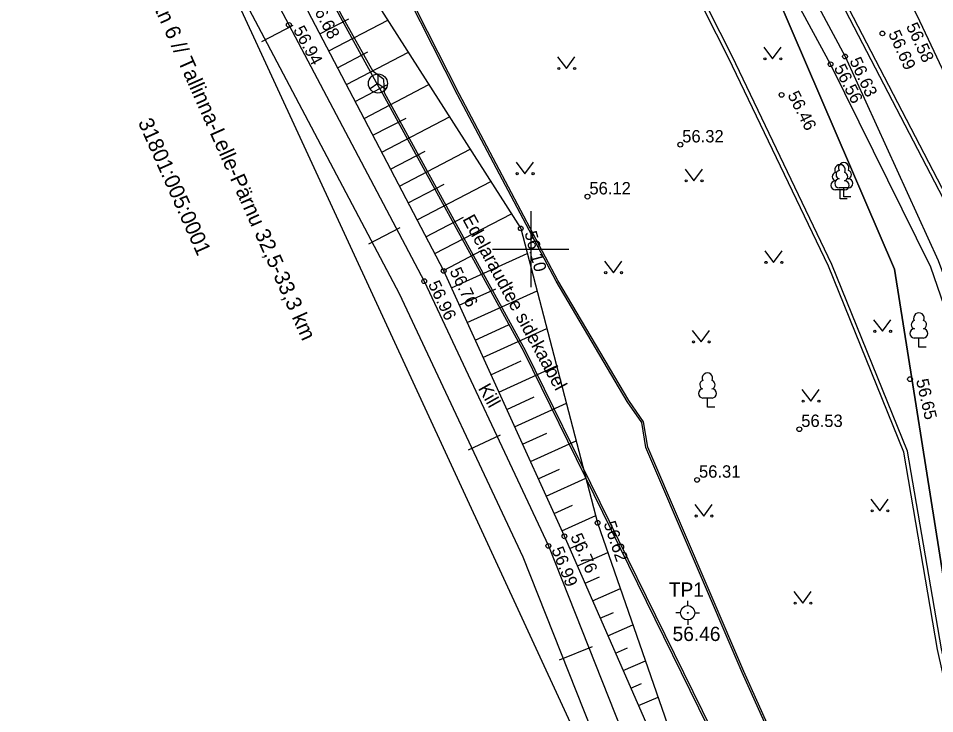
# Model space of a CAD drawing. Extents: x 542320 to 543602, y 6558748 to 6559969.
# Drawn here: x 542573.14 to 542621.18, y 6559275.64 to 6559312.11 of the extents above; entities that cross this region are included whole.
import ezdxf

# ---------------------------------------------------------------- set-up
doc = ezdxf.new("R2010")
doc.units = 0
for name, color, linetype in [('ALUSVORK', 7, 'Continuous'), ('HALJASTUS', 7, 'Continuous'), ('KORGUS-EH2000', 7, 'Continuous'), ('KPKAABEL', 7, 'Continuous'), ('mootpiir', 7, 'Continuous'), ('MPKAABEL', 7, 'Continuous'), ('PIIR', 7, 'Continuous'), ('PUU', 7, 'Continuous'), ('RDT', 7, 'Continuous'), ('RELJEEF', 7, 'Continuous'), ('SIKAEV', 7, 'Continuous'), ('SITRASS', 7, 'Continuous'), ('TEE', 7, 'Continuous'), ('VORK', 7, 'Continuous')]:
    doc.layers.add(name, color=color, linetype=linetype)

# ---------------------------------------------------------------- blocks, each defined once
blk = doc.blocks.new('VKORIS')
for p, q in [((0, 4), (0, -4)), ((-4, 0), (4, 0))]:
    blk.add_line(p, q)
blk = doc.blocks.new('SIKAEV')
for p, q in [((0, 1), (0, 0)), ((0, 0), (-0.83, -0.55)), ((0, 0), (0.83, -0.55))]:
    blk.add_line(p, q)
blk.add_circle((0, 0), 1)
blk = doc.blocks.new('LEHTP1')
for p, q in [((0.48, 0.95), (-0.48, 0.95)), ((0, 0), (0, 0.95)), ((0.76, 0), (0, 0))]:
    blk.add_line(p, q)
for centre, radius, start, end in [((0, 3.04), 0.554, 332.5799, 207.4201), ((-0.34, 2.345), 0.465, 109.02174, 253.14154), ((0.34, 2.345), 0.465, 286.85082, 70.98591), ((-0.475, 1.425), 0.475, 90.0016, 269.3953), ((0.475, 1.425), 0.475, 270.6047, 89.9984)]:
    blk.add_arc(centre, radius, start, end)
blk = doc.blocks.new('MURU')
for p, q in [((-0.927, 1.213), (0, 0)), ((0, 0), (0.891, 1.213))]:
    blk.add_line(p, q)
for centre in [(-0.802, 0), (0.856, 0)]:
    blk.add_circle(centre, 0.11)
blk = doc.blocks.new('SPYMAR')
for p, q in [((0, 0.75), (0, 1.25)), ((-0.75, 0), (-1.25, 0)), ((0.75, 0), (1.25, 0)), ((0, -0.75), (0, -1.25))]:
    blk.add_line(p, q)
for radius in [0.75, 0.044]:
    blk.add_circle((0, 0), radius)
blk = doc.blocks.new('RING02')
blk.add_circle((0, 0), 0.25)

msp = doc.modelspace()

# ---------------------------------------------------------------- linework, layer by layer
at = {"layer": 'KPKAABEL'}
for points in [[(542592.521, 6559362.446), (542597.547, 6559351.945), (542600.14, 6559344.366), (542606.118, 6559332.403), (542610.857, 6559323.162), (542616.273, 6559312.944), (542622.065, 6559301.812), (542626.969, 6559292.384), (542631.614, 6559283.754), (542633.958, 6559279.16), (542635.835, 6559275.606), (542642.325, 6559262.55)], [(542592.701, 6559362.532), (542597.732, 6559352.021), (542600.325, 6559344.443), (542606.296, 6559332.493), (542611.034, 6559323.254), (542616.45, 6559313.037), (542622.242, 6559301.904), (542627.146, 6559292.478), (542631.791, 6559283.847), (542634.136, 6559279.252), (542636.013, 6559275.697), (542642.504, 6559262.639)], [(542629.705, 6559255.548), (542624.459, 6559265.014), (542621.333, 6559278.998), (542619.565, 6559289.352), (542615.605, 6559299.115), (542610.376, 6559310.033), (542605.393, 6559319.873), (542600.368, 6559330.022), (542596.984, 6559338.198), (542596.381, 6559342.121), (542596.809, 6559346.972), (542595.758, 6559350.645), (542591.144, 6559359.29), (542590.252, 6559360.802)], [(542629.88, 6559255.645), (542624.648, 6559265.086), (542621.529, 6559279.037), (542619.758, 6559289.407), (542615.788, 6559299.196), (542610.555, 6559310.121), (542605.572, 6559319.963), (542600.55, 6559330.105), (542597.178, 6559338.252), (542596.582, 6559342.128), (542597.011, 6559346.991), (542595.944, 6559350.72), (542591.318, 6559359.388), (542590.424, 6559360.904)]]:
    msp.add_lwpolyline(points, dxfattribs=at)
at = {"layer": 'mootpiir'}
msp.add_lwpolyline([(542580.596, 6559350.501), (542576.13, 6559347.213), (542573.572, 6559344.253), (542570.527, 6559343.48), (542613.7, 6559249.972), (542615.953, 6559250.584), (542618.546, 6559251.554), (542622.286, 6559253.49), (542626.884, 6559255.347), (542629.88, 6559255.645), (542630.445, 6559256.8), (542630.818, 6559257.341), (542632.786, 6559258.084), (542634.681, 6559258.868), (542635.466, 6559259.163), (542639.905, 6559261.019), (542642.325, 6559262.55), (542647.794, 6559265.185), (542644.803, 6559292.129), (542641.558, 6559300.605), (542636.848, 6559320.338), (542627.616, 6559356.728)], dxfattribs=at)
at = {"layer": 'MPKAABEL'}
for points in [[(542622.093, 6559253.39), (542621.335, 6559255.374), (542617.705, 6559263.498), (542614.681, 6559269.795), (542611.089, 6559277.807), (542606.04, 6559289.597), (542605.819, 6559290.909), (542605.062, 6559292.013), (542601.327, 6559298.317), (542596.156, 6559308.103), (542592.302, 6559315.731), (542590.046, 6559320.195), (542585.68, 6559328.499), (542583.041, 6559333.495), (542580.391, 6559338.551), (542578.352, 6559342.398), (542575.831, 6559346.867)], [(542622.183, 6559253.436), (542621.427, 6559255.412), (542617.796, 6559263.54), (542614.772, 6559269.837), (542611.181, 6559277.847), (542606.137, 6559289.625), (542605.914, 6559290.947), (542605.146, 6559292.067), (542601.414, 6559298.366), (542596.245, 6559308.149), (542592.391, 6559315.776), (542590.135, 6559320.241), (542585.768, 6559328.546), (542583.129, 6559333.542), (542580.479, 6559338.598), (542578.44, 6559342.446), (542575.9, 6559346.947)]]:
    msp.add_lwpolyline(points, dxfattribs=at)
at = {"layer": 'PIIR'}
for points in [[(542456.68, 6559581.07), (542523.83, 6559477.46), (542537.52, 6559453.62), (542591.81, 6559358.92), (542597.79, 6559348.5), (542599.76, 6559343.89), (542619.08, 6559298.96), (542624.28, 6559266.08), (542637.46, 6559233.17), (542680, 6559143.81), (542700.43, 6559093.84), (542700.92, 6559090.29), (542704.02, 6559067.82)], [(542612.16, 6559350.51), (542632.63, 6559302.87), (542665.71, 6559205.86), (542667.87, 6559200.49), (542682.31, 6559164.31), (542683.94, 6559160.9), (542699.54, 6559124.27), (542718.47, 6559078.4), (542700.92, 6559090.29), (542700.43, 6559093.84), (542680, 6559143.81), (542637.46, 6559233.17), (542624.28, 6559266.08), (542619.08, 6559298.96), (542599.76, 6559343.89), (542612.16, 6559350.51)]]:
    msp.add_lwpolyline(points, dxfattribs=at)
at = {"layer": 'RDT'}
for points in [[(542570.527, 6559343.48), (542587.317, 6559311.762), (542594.415, 6559298.323), (542600.925, 6559284.44), (542609.327, 6559263.254), (542613.7, 6559249.972)], [(542569.237, 6559342.797), (542586.027, 6559311.079), (542593.108, 6559297.672), (542599.584, 6559283.86), (542607.954, 6559262.756), (542612.313, 6559249.515)], [(542585.902, 6559310.886), (542587.547, 6559311.755)], [(542591.507, 6559300.275), (542593.151, 6559301.144)], [(542596.731, 6559289.475), (542598.415, 6559290.265)], [(542601.506, 6559278.472), (542603.235, 6559279.158)]]:
    msp.add_lwpolyline(points, dxfattribs=at)
at = {"layer": 'RELJEEF'}
for points in [[(542611.276, 6559263.245), (542601.766, 6559284.942), (542595.436, 6559298.859), (542588.129, 6559312.865), (542578.066, 6559334.392), (542577.883, 6559336.16), (542579.736, 6559338.198), (542583.573, 6559340.233), (542588.18, 6559342.437), (542591.624, 6559344.187)], [(542591.624, 6559344.187), (542589.04, 6559341.17), (542585.552, 6559339.38), (542581.614, 6559337.235), (542580.482, 6559335.129), (542584.558, 6559325.434), (542590.137, 6559315.731), (542599.476, 6559301.09), (542603.506, 6559285.65), (542611.276, 6559263.245)], [(542588.951, 6559311.29), (542590.458, 6559312.077)], [(542589.413, 6559310.404), (542592.506, 6559312.017)], [(542589.876, 6559309.517), (542591.461, 6559310.344)], [(542590.338, 6559308.631), (542593.585, 6559310.325)], [(542590.801, 6559307.744), (542592.463, 6559308.611)], [(542591.263, 6559306.857), (542594.665, 6559308.632)], [(542591.726, 6559305.971), (542593.465, 6559306.878)], [(542592.188, 6559305.084), (542595.745, 6559306.94)], [(542592.651, 6559304.198), (542594.468, 6559305.145)], [(542593.113, 6559303.311), (542596.824, 6559305.247)], [(542594.038, 6559301.538), (542597.904, 6559303.554)], [(542593.576, 6559302.424), (542595.47, 6559303.413)], [(542594.501, 6559300.651), (542596.472, 6559301.68)], [(542594.964, 6559299.765), (542598.984, 6559301.862)], [(542595.426, 6559298.878), (542597.462, 6559299.94)], [(542595.841, 6559297.968), (542599.819, 6559299.777)], [(542596.255, 6559297.058), (542598.165, 6559297.927)], [(542596.669, 6559296.148), (542600.331, 6559297.813)], [(542597.083, 6559295.237), (542598.835, 6559296.034)], [(542597.497, 6559294.327), (542600.844, 6559295.849)], [(542597.911, 6559293.417), (542599.506, 6559294.142)], [(542598.325, 6559292.507), (542601.356, 6559293.885)], [(542598.739, 6559291.596), (542600.176, 6559292.25)], [(542599.153, 6559290.686), (542601.869, 6559291.921)], [(542599.567, 6559289.776), (542600.846, 6559290.358)], [(542599.981, 6559288.866), (542602.382, 6559289.957)], [(542600.395, 6559287.955), (542601.517, 6559288.465)], [(542600.809, 6559287.045), (542602.894, 6559287.993)], [(542601.223, 6559286.135), (542602.187, 6559286.573)], [(542601.638, 6559285.224), (542603.407, 6559286.029)], [(542602.043, 6559284.31), (542602.88, 6559284.677)], [(542602.444, 6559283.394), (542604.045, 6559284.096)], [(542602.846, 6559282.479), (542603.61, 6559282.813)], [(542603.247, 6559281.563), (542604.702, 6559282.2)], [(542603.649, 6559280.647), (542604.34, 6559280.95)], [(542604.05, 6559279.731), (542605.36, 6559280.305)], [(542604.452, 6559278.815), (542605.07, 6559279.086)], [(542604.853, 6559277.899), (542606.017, 6559278.409)], [(542605.254, 6559276.983), (542605.8, 6559277.222)], [(542605.656, 6559276.067), (542606.674, 6559276.514)]]:
    msp.add_lwpolyline(points, dxfattribs=at)
at = {"layer": 'SITRASS'}
for points in [[(542620.078, 6559252.347), (542619.611, 6559253.421), (542618.452, 6559255.17), (542617.973, 6559256.008), (542615.234, 6559262.86), (542599.652, 6559294.601), (542592.248, 6559308.146), (542591.915, 6559308.725), (542590.021, 6559312.164), (542581.41, 6559328.232), (542578.732, 6559334.135), (542575.622, 6559340.107), (542573.231, 6559344.166)], [(542620.167, 6559252.393), (542619.699, 6559253.469), (542618.919, 6559254.85), (542618.555, 6559255.685), (542618.063, 6559256.052), (542615.325, 6559262.901), (542599.741, 6559294.647), (542592.335, 6559308.195), (542592.292, 6559308.9), (542591.74, 6559309.316), (542590.109, 6559312.212), (542581.5, 6559328.276), (542578.822, 6559334.179), (542575.709, 6559340.156), (542573.331, 6559344.192)]]:
    msp.add_lwpolyline(points, dxfattribs=at)
at = {"layer": 'TEE'}
for points in [[(542624.102, 6559367.101), (542623.091, 6559366.625), (542619.655, 6559364.738), (542606.495, 6559357.531), (542598.927, 6559352.716), (542596.394, 6559351.262), (542597.483, 6559348.273), (542599.096, 6559344.51), (542601.523, 6559338.799), (542604.022, 6559333.449), (542609.839, 6559322.477), (542616.479, 6559310.106), (542621.369, 6559299.405), (542623.152, 6559294.601), (542623.728, 6559292.736), (542624.325, 6559289.249), (542624.923, 6559285.031), (542624.921, 6559280.093), (542625.11, 6559275.875), (542626.159, 6559270.713), (542630.818, 6559257.341)], [(542634.681, 6559258.868), (542630.146, 6559271.916), (542629.129, 6559276.409), (542628.98, 6559278.994), (542628.987, 6559283.205), (542628.787, 6559287.956), (542628.207, 6559291.798), (542627.216, 6559295.847), (542627.153, 6559296.256), (542626, 6559299.915), (542624.094, 6559304.138), (542620.263, 6559312.262), (542613.869, 6559324.503), (542608.179, 6559335.156), (542606.426, 6559338.985), (542605.717, 6559341.19), (542605.399, 6559342.931), (542605.274, 6559345.104), (542605.472, 6559347.122), (542606.079, 6559349.35), (542607.837, 6559352.387), (542608.749, 6559353.701), (542625.256, 6559362.999)], [(542630.445, 6559256.8), (542625.172, 6559270.111), (542624.375, 6559274.673), (542623.873, 6559280.787), (542623.665, 6559288.876), (542622.433, 6559294.202), (542622.365, 6559295.059), (542620.97, 6559299.05), (542615.719, 6559309.698), (542609.023, 6559322.07), (542603.292, 6559332.961), (542601.008, 6559337.652), (542600.271, 6559338.024), (542599.29, 6559338.496), (542598.116, 6559339.729), (542596.153, 6559343.676), (542594.87, 6559346.799)]]:
    msp.add_lwpolyline(points, dxfattribs=at)

# ---------------------------------------------------------------- block references
at = {"layer": 'ALUSVORK', "xscale": 0.5, "yscale": 0.5}
msp.add_blockref('SPYMAR', (542608.23, 6559280.93), dxfattribs=at)
at = {"layer": 'HALJASTUS', "xscale": 0.5, "yscale": 0.5}
for p in [(542612.68, 6559309.983), (542601.874, 6559309.473), (542599.694, 6559303.958), (542608.552, 6559303.587), (542612.734, 6559299.307), (542604.332, 6559298.767), (542618.439, 6559295.692), (542608.931, 6559295.135), (542614.682, 6559292.03), (542618.299, 6559286.283), (542609.07, 6559286.005), (542614.262, 6559281.436)]:
    msp.add_blockref('MURU', p, dxfattribs=at)
at = {"layer": 'KORGUS-EH2000', "xscale": 0.5, "yscale": 0.5}
for p in [(542587.317, 6559311.762), (542618.437, 6559311.314), (542616.479, 6559310.106), (542615.719, 6559309.698), (542613.152, 6559308.092), (542607.841, 6559305.482), (542602.975, 6559302.756), (542599.476, 6559301.09), (542595.436, 6559298.859), (542594.415, 6559298.323), (542619.886, 6559293.182), (542614.083, 6559290.559), (542608.721, 6559287.9), (542603.506, 6559285.65), (542601.766, 6559284.942), (542600.925, 6559284.44)]:
    msp.add_blockref('RING02', p, dxfattribs=at)
at = {"layer": 'PUU', "xscale": 0.5, "yscale": 0.5}
for p in [(542616.215, 6559302.634), (542616.411, 6559302.742), (542620.35, 6559294.867), (542609.264, 6559291.719)]:
    msp.add_blockref('LEHTP1', p, dxfattribs=at)
at = {"layer": 'SIKAEV', "xscale": 0.5, "yscale": 0.5}
msp.add_blockref('SIKAEV', (542591.992, 6559308.689), dxfattribs=at)
at = {"layer": 'VORK', "xscale": 0.5, "yscale": 0.5}
msp.add_blockref('VKORIS', (542600, 6559300), dxfattribs=at)

# ---------------------------------------------------------------- texts
at = {"layer": 'ALUSVORK'}
for s, p in [('TP1', (542607.241, 6559281.771)), ('56.46', (542607.437, 6559279.451))]:
    msp.add_text(s, height=0.75, dxfattribs=at).set_placement(p)
at = {"layer": 'KORGUS-EH2000'}
for s, rotation, p in [('56.68', 298.2389, (542588.42, 6559312.868)), ('56.94', 298.2389, (542587.529, 6559311.504)), ('56.58', 294.9694, (542619.665, 6559311.699)), ('56.69', 294.3346, (542618.73, 6559311.313)), ('56.56', 297.0695, (542615.875, 6559309.509)), ('56.63', 294.8998, (542616.697, 6559309.888)), ('56.46', 297.0695, (542613.445, 6559308.091)), ('56.10', 284.7727, (542599.667, 6559300.862)), ('56.76', 295.7734, (542595.731, 6559298.853)), ('56.96', 295.7734, (542594.602, 6559298.162)), ('56.65', 282.8507, (542620.197, 6559293.13)), ('56.62', 288.5357, (542603.811, 6559285.619)), ('56.76', 293.6058, (542602.065, 6559284.929)), ('56.99', 291.997, (542601.073, 6559284.244))]:
    msp.add_text(s, height=0.65, rotation=rotation, dxfattribs=at).set_placement(p)
for s, p in [('56.32', (542607.941, 6559305.599)), ('56.12', (542603.075, 6559302.873)), ('56.53', (542614.183, 6559290.676)), ('56.31', (542608.821, 6559288.017))]:
    msp.add_text(s, height=0.65, dxfattribs=at).set_placement(p)
at = {"layer": 'PIIR'}
for s, p in [('Jaama tn 6 // Tallinna-Lelle-Pärnu 32,5-33,3 km', (542578.851, 6559315.781)), ('31801:005:0001', (542579.395, 6559306.66))]:
    msp.add_text(s, height=0.8, rotation=294.0027, dxfattribs=at).set_placement(p)
at = {"layer": 'SITRASS'}
msp.add_text('Edelaraudtee sidekaabel', height=0.7, rotation=298.5384, dxfattribs=at).set_placement((542596.401, 6559301.577))
at = {"layer": 'TEE'}
msp.add_text('Kill', height=0.7, rotation=299.4082, dxfattribs=at).set_placement((542597.223, 6559292.705))

doc.saveas('drawing.dxf')
